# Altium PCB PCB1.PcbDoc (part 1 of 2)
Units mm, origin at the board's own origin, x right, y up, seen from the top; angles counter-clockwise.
Board outline 84 x 60 mm, 2 copper layers (Top Layer, Bottom Layer); 61 components, 46 nets, 218 pads, 307 vias.
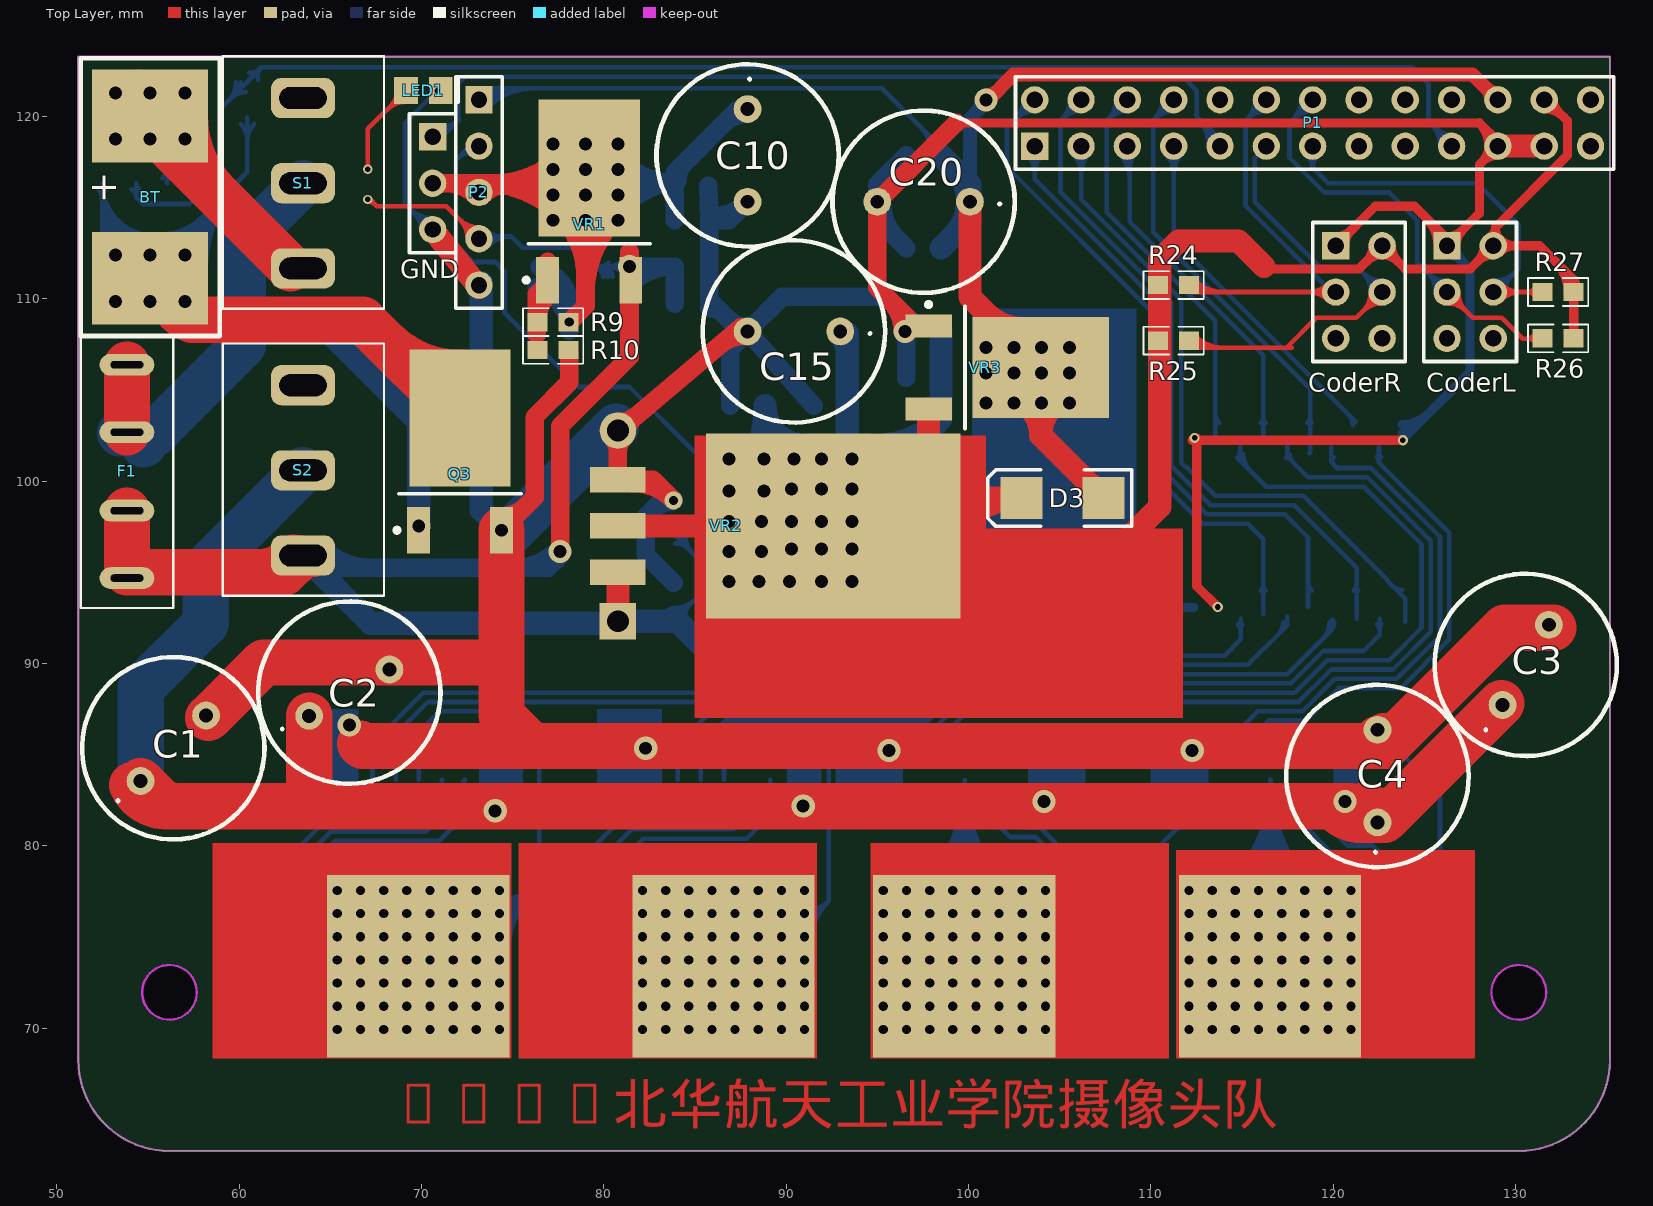
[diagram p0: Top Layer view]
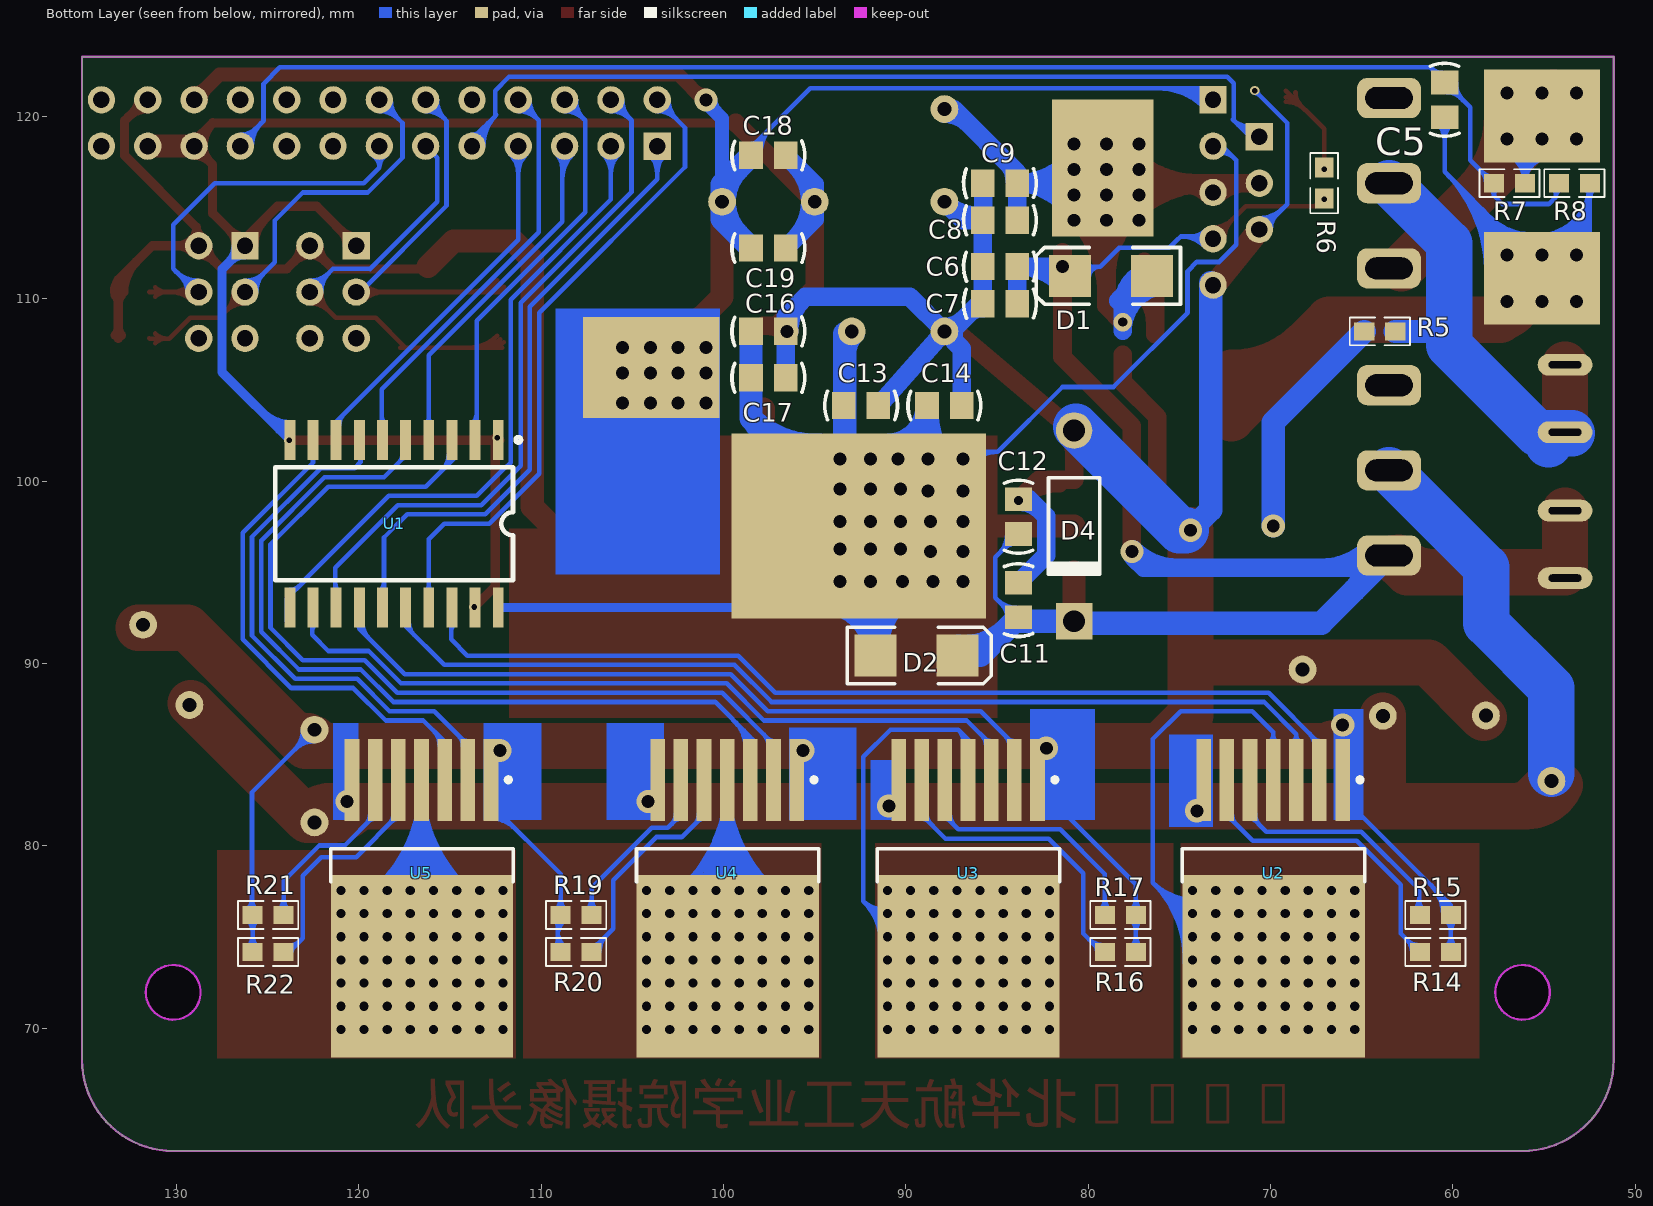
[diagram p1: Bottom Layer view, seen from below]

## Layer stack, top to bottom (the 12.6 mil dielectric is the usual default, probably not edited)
Top Layer: signal copper 0.0356
Dielectric: dielectric 0.32, FR-4, Dk 4.8
Bottom Layer: signal copper 0.0356

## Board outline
51.179,68.26 51.179,123.26 135.179,123.26 135.179,68.26 cw(c130.179,68.26) 130.179,63.26 56.179,63.26 cw(c56.179,68.26)
cut-out: 128.679,71.956 ccw(c130.179,71.956) 130.179,70.456 ccw(c130.179,71.956) 131.679,71.956 ccw(c130.179,71.956) 130.179,73.456 ccw(c130.179,71.956)
cut-out: 56.179,70.456 cw(c56.179,71.956) 54.679,71.956 cw(c56.179,71.956) 56.179,73.456 cw(c56.179,71.956) 57.679,71.956 cw(c56.179,71.956)

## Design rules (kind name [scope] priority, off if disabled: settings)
Clearance [All] p1: gap=0.254
ComponentClearance [All] p1 off: gap=0.254 collisioncheckmode=3 verticalgap=0.254 showdistances=FALSE
FabricationTestpoint [(IsPad And (OnTopLayer Or OnBottomLayer))] p1: side=3 testpointundercomponent=TRUE minsize=1.016 maxsize=2.54 preferedsize=1.524 minholesize=0 maxholesize=1.016 preferedholesize=0.813 testpointgrid=0.025 allowsidetop=TRUE allowsidebottom=TRUE usegrid=TRUE gridtolerance=0
HoleSize [All] p1: absolutevalues=TRUE maxlimit=5.08 minlimit=0.254 maxpercent=80.000 minpercent=20.000
PolygonConnect [All] p1: connectstyle=Relief reliefconductorwidth=0.254 reliefentries=4 polygonreliefangle="90 Angle"
RoutingVias [All] p1: holewidth=0.711 width=1.27 viastyle="Through Hole" minholewidth=0.305 minwidth=0.508 maxholewidth=0.711 maxwidth=1.27
SilkToSilkClearance [All] p1: silktosilkclearance=0
SilkscreenOverComponentPads [All] p1: minsilkscreentomaskgap=0
SolderMaskExpansion [All] p1: expansion=0.102
Width [All] p1: maxlimit=5.08 minlimit=0.254 preferedwidth=0.254
23 further rules are at their usual default settings.

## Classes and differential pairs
component class Driver: C1 C2 C3 C4 GND R14 R15 R16 R17 R19 R20 R21 R22 S2 U1 U2 U3 U4 U5
component class MCU: P1
component class Power: BT C5 C6 C7 C8 C9 C10 C11 C12 C13 C14 C15 C16 C17 C18 C19 C20 D1 D2 D3 D4 F1 LED1 P2 Q3 R5 R6 R7 R8 R9 R10 S1 VR1 VR2 VR3
component class Sensor: CoderL CoderR R24 R25 R26 R27

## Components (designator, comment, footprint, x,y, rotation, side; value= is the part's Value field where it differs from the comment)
BT "BAT" Header 55.118,115.57 r270 top
C1 "50V" C 56.388,85.344 r45 top locked
C2 "50V" C 66.04,88.392 r30 top locked
C3 "50V" C 130.556,89.916 r60 top locked
C4 "50V" C 122.428,83.82 r90 top locked
C5 "0805" C-RAD-0805 60.452,120.904 r270 bottom
C6 "Cap" C-RAD-0805 84.836,111.76 r180 bottom
C7 "Cap" C-RAD-0805 84.836,109.728 r180 bottom
C8 "Cap" C-RAD-0805 84.836,114.3 r180 bottom
C9 "Cap" C-RAD-0805 84.836,116.332 r180 bottom
C10 "16V" C 87.884,117.856 r270 top
C11 "Cap" C-RAD-0805 83.82,93.472 r270 bottom
C12 "Cap" C-RAD-0805 83.82,98.044 r270 bottom
C13 "Cap" C-RAD-0805 92.456,104.14 r0 bottom
C14 "Cap" C-RAD-0805 87.884,104.14 r0 bottom
C15 "16V" C 90.424,108.204 r180 top
C16 "Cap" C-RAD-0805 97.536,108.204 r0 bottom
C17 "Cap" C-RAD-0805 97.536,105.664 r0 bottom
C18 "Cap" C-RAD-0805 97.536,117.856 r0 bottom
C19 "Cap" C-RAD-0805 97.536,112.776 r0 bottom
C20 "16V" C 97.536,115.316 r180 top
CoderL "Header 3X2" HDR2X3 126.238,112.903 r270 top (schematic designator P6)
CoderR "Header 3X2" HDR2X3 120.142,112.903 r270 top (schematic designator P5)
D1 "Diode 1N5819" DIODE-SMB 78.74,111.252 r0 bottom
D2 "Diode 1N5819" DIODE-SMB 89.408,90.424 r180 bottom
D3 "Diode 1N5819" DIODE-SMB 105.156,99.06 r180 top
D4 "Diode 1N4007" DIO10.46-5.3x2.8 80.772,97.536 r270 bottom
F1 "10A" "保险丝  15A" 53.848,100.584 r270 top
GND "byBAT" HDR1X3 70.612,118.872 r270 top (schematic designator Servo1)
LED1 "GREEN" LED_0805 70.104,121.412 r0 top
P1 "toDriver" HDR2X13_CEN 103.632,118.364 r0 top
P2 "TEXT" HDR1X5 73.152,120.904 r270 top
Q3 "IR7843" IRLR7843 72.136,101.6 r90 top
R5 "Res1" 0603-1 64.008,108.204 r180 bottom
R6 "Res1" 0603-1 67.056,116.332 r270 bottom
R7 "Res1" 0603-1 56.896,116.332 r180 bottom
R8 "Res1" 0603-1 53.34,116.332 r0 bottom
R9 "Res1" 0603-1 77.216,108.712 r0 top
R10 "Res1" 0603-1 77.216,107.188 r180 top
R14 "Res1" 0603-1 60.96,74.168 r0 bottom locked
R15 "Res1" 0603-1 60.96,76.2 r0 bottom locked
R16 "Res1" 0603-1 78.232,74.168 r0 bottom locked
R17 "Res1" 0603-1 78.232,76.2 r0 bottom locked
R19 "Res1" 0603-1 108.077,76.2 r180 bottom locked
R20 "Res1" 0603-1 108.077,74.168 r180 bottom locked
R21 "Res1" 0603-1 124.968,76.2 r180 bottom locked
R22 "Res1" 0603-1 124.968,74.168 r180 bottom locked
R24 "Res1" 0603-1 111.252,110.744 r180 top
R25 "Res1" 0603-1 111.252,107.696 r180 top
R26 "Res1" 0603-1 132.334,107.823 r0 top
R27 "Res1" 0603-1 132.334,110.363 r0 top
S1 "ALL" BK1 63.5,116.332 r180 top
S2 "Motor" BK1 63.5,100.584 r180 top
U1 "74LS244" 74ALS244 111.252,102.108 r270 bottom
U2 "BTN_7971" BTN_7971B 65.564,81.28 r270 bottom locked
U3 "BTN_7971" BTN_7971B 82.296,81.28 r270 bottom locked
U4 "BTN_7971" BTN_7971B 95.504,81.28 r270 bottom locked
U5 "BTN_7971" BTN_7971B 112.268,81.28 r270 bottom locked
VR1 "AMS1085 adj" "AMS 1085CD" 79.248,115.316 r0 top
VR2 "AMS1085 5.0" TO-263-3L 81.788,97.536 r270 top
VR3 "AMS1085 3.3" "AMS 1085CD" 102.108,106.172 r270 top

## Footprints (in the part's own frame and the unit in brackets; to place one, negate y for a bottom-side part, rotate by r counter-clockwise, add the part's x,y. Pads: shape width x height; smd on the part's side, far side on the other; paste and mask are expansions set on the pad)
74ALS244 [mm]
  rect 2.2x0.6 smd: 1(-0.15,-1.1) 2(-0.15,-2.37) 3(-0.15,-3.64) 4(-0.15,-4.91) 5(-0.15,-6.18) 6(-0.15,-7.45) 7(-0.15,-8.72) 8(-0.15,-9.99) 9(-0.15,-11.26) 10(-0.15,-12.53) 11(9.05,-12.53) 12(9.05,-11.26) 13(9.05,-9.99) 14(9.05,-8.72) 15(9.05,-7.45) 16(9.05,-6.18) 17(9.05,-4.91) 18(9.05,-3.64) 19(9.05,-2.37) 20(9.05,-1.1)
  silkscreen extent -0.3,-13.34 7.55,0.15
0603-1 [mm] "贴片带丝印"
  rect 1.1x1 smd: 1(-0.85,0) 2(0.85,0)
  silkscreen extent -1.65,-0.76 1.65,0.76, body extent -1.14,-0.38 1.14,0.38, height 1
"AMS 1085CD" [mm]
  rect 1.25x2.55 smd: 1(-2.331,-4.3) 3(2.229,-4.3)
  rect 5.55x7.5 smd: 2(-0.051,1.85)
  rect 5.55x7.5 smd far side: 2(-0.051,1.854)
  silkscreen extent -3.63,-4.42 3.3,-2.3, body extent -3.43,-2.15 3.32,4.07, height 2.38
BK1 [mm]
  rrect50% 3.5x2.2 hole 1.2 slot 2.6 at 0 deg: 1(0,4.67) 2(0,0) 3(0,-4.67)
  silkscreen extent -4.45,-6.96 4.39,6.88
BTN_7971B [mm]
  rect 10x10 smd far side: 0(7.896,-4.267)
  rect 4.5x0.8 smd: 1(-2.334,-0.483) 2(-2.334,-1.753) 3(-2.334,-3.023) 4(-2.334,-4.293) 5(-2.334,-5.563) 6(-2.334,-6.833) 7(-2.334,-8.103)
  rect 10x10 smd: 8(7.896,-4.267)
  silkscreen extent -2.46,-9.27 3.25,0.73, body extent 1.45,-9.27 10.7,0.73, height 4.4
C [mil]
  round 60 hole 30: 1(-100,0) 2(100,0)
  silkscreen extent -197,-197 197,197
C-RAD-0805 [mm] "贴片电容"
  rect 1.3x1.5 smd: 1(-0.95,0) 2(0.95,0)
  silkscreen extent -2,-0.79 2,0.79, body extent -1.27,-0.64 1.27,0.64, height 0.9
DIO10.46-5.3x2.8 [mm] "Diode, Axial; Body 5.2 x 2.7 mm (LxDia. max), Lead Dia. 0.86 mm (max)"
  round 2 hole 1.2: 1(-5.23,0)
  rect 2x2 hole 1.2: 2(5.23,0)
  silkscreen extent -2.65,-1.4 2.75,1.4
DIODE-SMB [mm] "DO-214-AA/SMB; 2 C-Bend Leads; Body 5.3 x 3.6 mm, inc. leads (LxW)"
  rect 2.3x2.3 smd: 1(-2.25,0) 2(2.25,0)
  silkscreen extent -3.8,-1.55 4.1,1.55
HDR1X3 [mm] "Connector; Header; 3 Position"
  rect 1.5x1.5 hole 0.9: 1(0,0)
  round 1.5 hole 0.9: 2(2.54,0) 3(5.08,0)
  silkscreen extent -1.27,-1.27 6.35,1.27
HDR1X5 [mm] "Connector; Header; 5 Position"
  rect 1.5x1.5 hole 0.9: 1(0,0)
  round 1.5 hole 0.9: 2(2.54,0) 3(5.08,0) 4(7.62,0) 5(10.16,0)
  silkscreen extent -1.27,-1.27 11.43,1.27
HDR2X3 [mm] "Connector; Header; 3x2 Position"
  rect 1.5x1.5 hole 0.9: 1(0,0)
  round 1.5 hole 0.9: 2(0,2.54) 3(2.54,0) 4(2.54,2.54) 5(5.08,0) 6(5.08,2.54)
  silkscreen extent -1.27,-1.27 6.35,3.81
HDR2X13_CEN [mm] "Connector; Header; 13x2 Position"
  rect 1.5x1.5 hole 0.9: 1(0,0)
  round 1.5 hole 0.9: 2(2.54,0) 3(5.08,0) 4(7.62,0) 5(10.16,0) 6(12.7,0) 7(15.24,0) 8(17.78,0) 9(20.32,0) 10(22.86,0) 11(25.4,0) 12(27.94,0) 13(30.48,0) 14(0,2.54) 15(2.54,2.54) 16(5.08,2.54) 17(7.62,2.54) 18(10.16,2.54) 19(12.7,2.54) 20(15.24,2.54) 21(17.78,2.54) 22(20.32,2.54) 23(22.86,2.54) 24(25.4,2.54) 25(27.94,2.54) 26(30.48,2.54)
  silkscreen extent -1.06,-1.27 31.75,3.81
Header [mm]
  rect 5.08x6.35 smd: 1(-4.445,0) 2(4.445,0)
  rect 5.08x6.35 smd far side: 1(-4.445,0) 2(4.445,0)
  silkscreen extent -7.62,-3.81 7.62,3.81
IRLR7843 [mm]
  rect 2.55x1.25 smd: 1(-4.3,2.305) 3(-4.3,-2.255)
  rect 7.5x5.55 smd: 4(1.85,0.025)
  silkscreen extent -4.42,-3.32 -2.3,3.6, body extent -2.15,-3.35 4.07,3.4, height 2.38
LED_0805 [mm] "贴片二极管"
  rect 1.3x1.5 smd: 1(-0.95,0) 2(0.95,0)
  silkscreen extent 1.91,-0.64 1.91,0.64
TO-263-3L [mil]
  rect 55x120 smd: 1(-100,-40) 2(0,-40) 3(100,-40)
  rect 400x550 smd: 2(0,425)
  rect 400x550 smd far side: 2(0,425)
"保险丝  15A" [mm]
  oval 1.2x3 hole 0.4 slot 1.8 at 90 deg: 1(-5.79,0) 1(-2.09,0) 2(2.21,0) 2(5.91,0)
  silkscreen extent -7.44,-2.54 7.54,2.54

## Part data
BT: library part Header
C1 C2 C3 C4 C10 C15 C20: library part "Cap Pol1", "Polarized Capacitor (Radial)"
C5: library part "Cap Pol3", "Polarized Capacitor (Surface Mount)"
C6 C7 C8 C9 C11 C12 C13 C14 C16 C17 C18 C19: "无极性电容"
CoderL CoderR: "Header, 3-Pin, Dual row"
D1 D2 D3: library part "Diode 1N4007", "1 Amp General Purpose Rectifier"
D4: "1 Amp General Purpose Rectifier"
F1: library part "Fuse 1", "Fuse"
GND: library part "Header 3", "Header, 3-Pin"
LED1: library part LED2, "Typical RED, GREEN, YELLOW, AMBER GaAs LED"
P1: library part "Header 13X2A", "Header, 13-Pin, Dual row"
P2: library part "Header 5", "Header, 5-Pin"
Q3: library part MOSFET-N, "N-Channel MOSFET"
R5 R6 R7 R8 R9 R10 R14 R15 R16 R17 R19 R20 R21 R22 R24 R25 R26 R27: "贴片电阻"
S1 S2: library part SW-SPDT, "SPDT Subminiature Toggle Switch, Right Angle Mounting, Vertical Actuation"
VR1 VR2 VR3: library part AMS1085

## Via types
v1: diameter 0.762, hole 0.508, Top Layer to Bottom Layer, 224 vias
v2: diameter 1.27, hole 0.711, Top Layer to Bottom Layer, 75 vias
v3: diameter 0.559, hole 0.305, Top Layer to Bottom Layer, 3 vias
v4: diameter 0.508, hole 0.305, Top Layer to Bottom Layer, 3 vias
v5: diameter 1, hole 0.5, Top Layer to Bottom Layer, 2 vias

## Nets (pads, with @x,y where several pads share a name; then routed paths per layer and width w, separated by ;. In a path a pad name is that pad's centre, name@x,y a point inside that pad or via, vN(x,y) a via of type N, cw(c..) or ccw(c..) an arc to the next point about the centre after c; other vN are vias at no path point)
GND: C1.2 C2.2 C3.2 C4.2 C6.1 C7.1 C8.1 C9.1 C10.2 C11.1 C12.1 C13.1 C14.1 C15.2 C16.1 C17.1 C18.1 C19.1 C20.2 CoderL.1 CoderR.1 D4.1 GND.3 LED1.2 P1.11 P1.12 P2.5 Q3.3 R10.1 R14.1 R15.1 R16.1 R17.1 R19.1 R20.1 R21.1 R22.1 U1.1 U1.10 U1.19 U2.1 U3.1 U4.1 U5.1 VR2.1 VR3.1 | length 424.2
  Top Layer w0.508: 99.314,119.634 128.016,119.634 P1.11@129.032,118.618 ; v3@112.268,102.235 v3@112.522,102.235 ; v3@112.377,102.344 cw(c112.027,101.994) 112.522,101.994 ; v3@112.413,102.38 ccw(c112.763,102.73) 112.763,102.235 ; v3@112.522,102.362 v3@112.522,102.235 ; v3(113.665,93.091) 112.522,94.234 v3@112.522,102.235 ; CoderR.1@120.142,113.399 ccw(c120.142,114.596) 120.989,113.75 ccw(c121.835,112.903) CoderR.1@120.638,112.903 ; CoderR.1@120.269,113.03 122.301,115.062 124.46,115.062 126.238,113.284 CoderL.1@126.238,112.903 128.016,114.681 128.016,117.348 P1.11@129.032,118.364 ; v3(123.825,102.235) v3@112.522,102.235 ; 125.122,114.4 cw(c123.625,112.903) CoderL.1@125.742,112.903 ; CoderL.1@126.238,113.399 ccw(c126.238,114.596) 127.085,113.75 ccw(c127.931,112.903) CoderL.1@126.734,112.903 ; 128.006,119.644 cw(c126.725,118.364) 128.536,118.364 cw(c127.339,118.364) 128.185,117.517 cw(c129.032,116.671) P1.11@129.032,117.868 ; 128.619,119.031 ccw(c129.032,119.444) P1.11@129.032,118.86
  Top Layer w1.016: v2(74.391,97.3) 76.2,99.109 76.2,103.505 78.105,105.41 R10.1@78.105,106.934 ; Q3.3@74.391,98.067 ccw(c74.391,99.919) 75.7,98.609 ; D4.1@80.424,102.418 cw(c79.584,101.578) 80.772,101.578 cw(c81.96,101.578) D4.1@81.12,102.418 ; D4.1@80.772,102.766 D4.1@80.772,102.616 ; D4.1@80.813,103.256 ccw(c80.921,104.55) 81.76,103.559 ; D4.1@81.262,102.725 cw(c82.336,102.636) 81.64,103.458 ; VR2.1@81.597,99.885 cw(c81.597,96.819) v5@83.766,98.987 ; VR2.1@81.66,99.896 cw(c82.15,98.47) 83.217,99.536 ; v5@83.693,99.06 82.677,100.076 VR2.1@80.772,100.076 D4.1@80.772,102.616 ; 86.395,107.481 cw(c87.696,105.944) C15.2@87.863,107.951 ; C15.2@87.505,108.421 80.719,102.679 D4.1@80.772,102.616 ; 95.675,109.938 cw(c93.94,108.204) v2@96.393,108.204 ; VR3.1@96.61,108.114 cw(c97.548,107.176) VR3.1@97.548,108.503 ; VR3.1@97.808,108.503 97.11,108.503 94.996,110.617 C20.2@94.996,115.316 99.314,119.634
  Top Layer w1.27: GND.3@70.612,113.792 P2.5@73.152,110.617 ; P1.11@129.032,118.364 P1.12@131.572,118.364
  Top Layer w2.54: C1.2@58.311,87.013 61.341,90.043 74.041,90.043 ; 66.634,85.598 66.761,85.471 76.073,85.471 ; v2(74.391,97.3) 74.391,87.153 76.073,85.471 ; 121.508,85.471 ccw(c121.508,87.28) C4.2@122.787,86.001 ; C4.2@122.428,85.852 ccw(c122.428,87.964) 123.921,86.47 ; C3.2@132.08,91.948 129.399,91.948 122.922,85.471 76.073,85.471
  Bottom Layer w0.254: R14.1@59.846,74.432 ccw(c59.21,75.068) 60.11,75.068 ccw(c61.011,75.068) R14.1@60.374,74.432 ; R15.1@59.846,75.936 cw(c59.21,75.3) 60.11,75.3 cw(c61.011,75.3) R15.1@60.374,75.936 ; R15.1@60.025,76.2 cw(c61.14,76.2) 60.352,76.989 ; R15.1@60.071,76.2 60.11,76.161 R14.1@60.11,74.168 ; R15.1@60.11,76.2 60.11,76.747 65.786,82.423 U2.1@66.04,82.423 ; R15.1@60.279,76.2 cw(c62.008,76.2) 60.785,77.422 ; R15.1@60.533,76.2 cw(c62.875,76.2) 61.219,77.856 ; 69.332,114.945 ccw(c70.612,116.226) GND.3@70.612,114.415 ; 69.638,114.639 cw(c68.792,113.792) GND.3@69.989,113.792 ; 69.765,114.512 ccw(c70.612,115.358) GND.3@70.612,114.161 ; GND.3@70.612,113.792 70.485,113.792 69.088,115.189 69.088,119.634 v4@70.739,121.285 ; v4@70.739,121.412 cw(c70.432,121.412) 70.649,121.195 cw(c70.866,120.978) v4@70.866,121.285 ; R16.1@77.118,74.432 ccw(c76.482,75.068) 77.382,75.068 ccw(c78.283,75.068) R16.1@77.646,74.432 ; R17.1@77.118,75.936 cw(c76.482,75.3) 77.382,75.3 cw(c78.283,75.3) R17.1@77.646,75.936 ; R17.1@77.118,76.464 ccw(c76.482,77.1) 77.382,77.1 ccw(c78.283,77.1) R17.1@77.646,76.464 ; R16.1@77.382,74.168 77.382,75.985 R17.1@77.47,76.073 ; R17.1@77.382,76.2 77.382,77.89 82.042,82.55 U3.1@82.931,82.55 ; R19.1@108.663,76.464 ccw(c108.026,77.1) 108.927,77.1 ccw(c109.827,77.1) R19.1@109.191,76.464 ; R20.1@108.712,74.383 R20.1@108.927,74.168 109.093,74.334 R19.1@109.093,76.2 ; R20.1@108.713,74.432 ccw(c107.796,75.349) 109.093,75.349 ; R19.1@108.713,75.936 cw(c107.796,75.019) 109.093,75.019 ; R20.1@108.893,74.252 ccw(c108.41,74.735) 109.093,74.735 ; R19.1@108.893,76.116 cw(c108.41,75.633) 109.093,75.633 ; R20.1@108.927,73.953 R20.1@108.966,73.914 ; R19.1@108.927,76.2 108.927,78.447 U5.1@112.649,82.169 ; 109.093,74.788 ccw(c109.597,74.788) R20.1@109.241,74.432 ; 109.093,75.58 cw(c109.597,75.58) R19.1@109.241,75.936 ; 111.419,80.939 cw(c112.751,79.608) U5.1@112.751,81.491 ; 111.853,81.373 cw(c112.751,80.475) U5.1@112.751,81.745 ; 112.287,81.807 cw(c112.751,81.343) U5.1@112.751,81.999 ; U5.1@112.72,82.24 cw(c112.751,82.21) U5.1@112.751,82.253 ; C4.2@122.428,85.725 cw(c122.428,84.192) 123.512,85.276 cw(c124.596,86.36) C4.2@123.063,86.36 ; C4.2@122.428,85.979 cw(c122.428,85.059) 123.078,85.71 cw(c123.729,86.36) C4.2@122.809,86.36 ; C4.2@122.428,86.36 125.857,82.931 R21.1@125.857,76.239 ; R22.1@125.554,74.432 ccw(c124.917,75.068) 125.818,75.068 ccw(c126.718,75.068) R22.1@126.082,74.432 ; R21.1@125.554,75.936 cw(c124.917,75.3) 125.818,75.3 cw(c126.718,75.3) R21.1@126.082,75.936 ; R21.1@125.604,76.464 ccw(c124.994,77.074) 125.857,77.074 ; R21.1@125.818,76.2 125.818,74.207 R22.1@125.857,74.168 ; 125.857,77.127 ccw(c126.795,77.127) R21.1@126.132,76.464
  Bottom Layer w0.508: U1.10@123.782,102.258 127.496,105.972 127.496,111.621 126.492,112.625 CoderL.1@126.492,112.776 ; U1.10@123.782,102.596 ccw(c123.782,103.412) 124.359,102.835 ; U1.10@123.782,103.104 ccw(c123.782,105.146) 125.226,103.702 ; CoderL.1@126.238,112.407 cw(c126.238,111.267) 127.044,112.073 ; CoderL.1@126.734,112.903 ccw(c127.989,112.903) 127.102,112.015
  Bottom Layer w1.016: 82.662,98.414 cw(c83.72,97.356) C12.1@83.72,98.852 ; 82.743,98.495 cw(c83.82,97.419) C12.1@83.82,98.941 ; C11.1@83.82,94.422 82.308,95.934 82.308,98.06 83.242,98.994 C12.1@83.82,98.994 ; C9.1@85.725,116.205 C8.1@85.786,114.3 ; C7.1@85.786,109.486 cw(c85.786,108.436) 86.529,109.178 ; C8.1@85.797,114.542 ccw(c85.996,117.203) C10.2@87.884,115.316 86.868,114.3 C8.1@85.786,114.3 ; 86.8,108.907 ccw(c87.884,109.991) C15.2@87.884,108.458 ; C14.1@86.934,104.14 86.934,107.254 87.376,107.696 87.376,108.331 85.786,109.921 C6.1@85.786,111.76 C8.1@85.786,114.3 ; C13.1@91.506,104.14 C15.2@87.884,108.204 89.789,110.109 95.504,110.109 96.586,109.027 C17.1@96.586,105.664 ; 95.675,109.938 cw(c93.94,108.204) C16.1@96.393,108.204 ; 95.832,109.781 cw(c94.356,108.304) C16.1@96.444,108.304 ; C19.1@96.101,113.261 cw(c98.157,115.316) 95.25,115.316 cw(c98.157,115.316) C18.1@96.101,117.371 ; C19.1@96.586,112.776 94.996,114.366 C20.2@94.996,115.316 94.996,116.266 C18.1@96.586,117.856
  Bottom Layer w1.27: P2.5@73.279,110.871 73.279,98.412 v2(74.391,97.3)
  Bottom Layer w2.54: v2@74.641,97.3 74.995,97.3 D4.1@80.669,102.973
  other v2: 95.631,85.217 112.268,85.217 82.296,85.344 66.04,86.614 96.52,108.204
  other v3: 112.395,102.362
  other v4: 70.866,121.412
  other v5: 83.82,98.933
GND_BAT: BT.2 C5.2 Q3.4 R8.1 | length 137.6
  Top Layer w2.54: BT.2@54.483,112.395 ccw(c56.016,112.395) BT.2@54.932,111.311 ; BT.2@55.118,110.49 cw(c55.118,108.957) BT.2@56.202,110.041 ; BT.2@55.264,110.979 57.404,108.839 66.772,108.839 Q3.4@72.161,103.45 ; BT.2@56.574,109.406 ccw(c57.943,110.775) BT.2@57.943,108.839 ; 67.964,107.648 ccw(c72.111,111.795) Q3.4@72.111,105.93
  Bottom Layer w0.254: R8.1@52.226,116.068 cw(c51.59,115.432) 52.49,115.432 ; BT.2@52.451,113.157 52.49,113.196 R8.1@52.49,116.332 ccw(c55.357,116.332) BT.2@54.882,113.505 ; BT.2@52.49,113.33 ccw(c54.853,113.33) BT.2@54.462,111 ; BT.2@52.49,113.63 ccw(c54.903,113.63) BT.2@54.504,111.25 ; 52.49,113.931 ccw(c54.954,113.931) BT.2@54.546,111.501 ; 52.49,114.231 ccw(c55.004,114.231) BT.2@54.588,111.751 ; 52.49,114.531 ccw(c55.054,114.531) BT.2@54.63,112.002 ; 52.49,114.831 ccw(c55.105,114.831) BT.2@54.672,112.252 ; 52.49,115.131 ccw(c55.155,115.131) BT.2@54.714,112.503 ; 52.49,115.732 ccw(c55.256,115.732) BT.2@54.798,113.004 ; R8.1@52.49,116.032 ccw(c55.306,116.032) BT.2@54.84,113.254 ; R8.1@52.754,116.068 ccw(c53.391,115.432) 52.49,115.432 ; BT.2@54.756,112.753 cw(c55.206,115.431) 52.49,115.431 ; BT.2@55.118,111.125 BT.2@57.404,108.839 ; BT.2@55.436,110.807 ccw(c56.606,111.978) BT.2@56.925,110.353 ; BT.2@55.753,113.284 ccw(c55.753,115.737) 57.487,114.002 ; BT.2@55.753,113.538 ccw(c55.753,116.604) 57.921,114.436 ; BT.2@55.773,110.47 ccw(c56.717,111.415) BT.2@56.974,110.104 ; BT.2@56.11,110.133 ccw(c56.828,110.851) v2(57.023,109.855) ; BT.2@56.25,113.486 ccw(c56.481,114.588) 57.277,113.792 ; BT.2@56.388,111.144 cw(c60.336,111.265) 57.543,114.058 ; BT.2@56.642,111.152 cw(c61.142,111.289) 57.958,114.473 ; BT.2@56.748,112.822 ccw(c56.124,113.792) 57.277,113.792 ; BT.2@56.885,112.609 ccw(c56.423,113.326) BT.2@57.277,113.326 ; BT.2@56.895,111.16 cw(c61.949,111.314) 58.374,114.889 ; BT.2@57.149,111.168 cw(c62.755,111.339) 58.789,115.304 ; BT.2@57.277,113.008 ccw(c57.636,113.008) BT.2@57.382,112.754 ; BT.2@57.277,113.03 57.277,113.792 ; BT.2@57.277,113.271 ccw(c57.899,113.271) BT.2@57.459,112.831 ; BT.2@57.403,111.175 cw(c63.562,111.363) 59.205,115.72 ; BT.2@57.657,111.183 cw(c64.368,111.388) 59.621,116.136 ; BT.2@57.911,111.191 cw(c65.175,111.412) 60.036,116.551 ; BT.2@58.165,111.199 cw(c65.982,111.437) 60.452,116.967 ; C5.2@60.082,119.584 cw(c59.189,118.691) 60.452,118.691 cw(c61.715,118.691) C5.2@60.822,119.584 ; C5.2@60.452,119.954 60.452,116.967 ; 57.277,113.792 60.452,116.967
  other v2: 53.213,109.855 55.118,109.855 53.213,112.395 55.118,112.395 57.023,112.395
NetC5_1: C5.1 P1.10 R7.1 R8.2 | length 91.9
  Bottom Layer w0.254: R8.2@54.081,115.995 cw(c53.877,115.561) 54.356,115.561 ; 54.356,115.712 cw(c54.86,115.712) R8.2@54.504,116.068 ; R8.2@54.356,116.332 54.356,115.57 54.737,115.189 57.277,115.189 57.746,115.658 ; R7.1@57.548,116.016 cw(c57.324,115.658) 57.746,115.658 ; R7.1@57.746,116.332 57.746,115.658 ; R7.1@57.785,116.332 59.055,117.602 59.055,120.496 60.413,121.854 C5.1@60.452,121.854 ; R7.1@57.796,116.705 ccw(c57.796,117.579) 58.414,116.961 ; R7.1@57.944,116.016 ccw(c58.168,115.658) 57.746,115.658 ; R7.1@58.169,116.332 cw(c59.096,116.332) 58.441,116.988 ; 59.416,120.857 ccw(c58.419,121.854) C5.1@59.829,121.854 ; 59.564,121.004 cw(c60.352,120.216) C5.1@60.352,121.331 ; C5.1@59.85,121.29 ccw(c59.286,121.854) C5.1@60.083,121.854 ; C5.1@60.325,121.793 61.214,122.682 ; C5.1@60.552,122.377 ccw(c60.552,123.239) 61.161,122.629 ; C5.1@61.051,122.012 cw(c61.683,122.213) 61.214,122.682 ; 125.339,119.644 cw(c124.058,118.364) P1.10@125.869,118.364 ; 125.645,119.338 ccw(c126.492,120.184) P1.10@126.492,118.987 ; 125.772,119.211 cw(c124.926,118.364) P1.10@126.123,118.364 ; P1.10@126.492,118.364 126.492,118.491 125.222,119.761 125.222,121.793 124.333,122.682 61.214,122.682
NetF1_1: F1.1 R5.2 S1.2 | length 26.8
  Top Layer w0.254: F1.1@53.848,106.374 F1.1@54.154,106.68
  Top Layer w2.54: F1.1@53.848,102.674 F1.1@53.848,106.374
  Bottom Layer w0.254: F1.1@53.848,102.674 F1.1@54.668,102.674
  Bottom Layer w1.27: 60.322,108.204 R5.2@63.158,108.204
  Bottom Layer w2.54: F1.1@53.467,102.616 55.372,102.616 60.195,107.439 60.195,113.04 63.487,116.332 S1.2@63.5,116.332 ; 54.748,102.004 ccw(c54.748,102.034) 54.769,102.013
NetLED1_1: LED1.1 R6.1 | length 8.4
  Top Layer w0.254: v4@66.966,117.184 ccw(c66.749,117.401) 67.056,117.401 ccw(c67.363,117.401) v4@67.146,117.184 ; v4(67.056,117.094) 67.056,119.314 LED1.1@69.154,121.412 ; 68.09,120.348 cw(c69.154,119.285) LED1.1@69.154,120.789 ; 68.332,120.59 ccw(c67.61,121.312) LED1.1@68.631,121.312 ; LED1.1@68.524,120.782 cw(c69.154,120.152) LED1.1@69.154,121.043
NetP1_1: P1.1 U1.15 | length 38.3
  Bottom Layer w0.254: P1.1@103.191,117.923 cw(c102.128,116.86) 103.632,116.86 cw(c105.136,116.86) P1.1@104.073,117.923 ; P1.1@103.371,118.103 cw(c102.741,117.473) 103.632,117.473 cw(c104.523,117.473) P1.1@103.893,118.103 ; P1.1@103.632,118.364 103.632,116.542 110.617,109.557 110.617,100.617 113.063,98.171 117.348,98.171 118.618,96.901 U1.15@118.618,93.091 ; 118.618,94.478 ccw(c119.322,94.478) U1.15@118.824,93.98
NetP1_2: P1.2 U1.11 | length 40.9
  Bottom Layer w0.254: P1.2@105.731,117.923 cw(c104.668,116.86) 106.172,116.86 cw(c107.676,116.86) P1.2@106.613,117.923 ; P1.2@105.911,118.103 cw(c105.281,117.473) 106.172,117.473 cw(c107.063,117.473) P1.2@106.433,118.103 ; 106.172,115.57 106.172,115.824 ; P1.2@106.172,118.364 106.172,115.824 ; 123.263,94.246 ccw(c123.782,94.765) U1.11@123.782,94.031 ; U1.11@123.952,92.284 123.952,93.557 122.97,94.539 122.97,94.581 118.364,99.187 113.538,99.187 111.948,100.777 111.894,100.777 111.671,101 111.671,109.94 106.172,115.439 106.172,115.824
NetP1_3: P1.3 U1.4 | length 23.4
  Bottom Layer w0.254: P1.3@108.271,117.923 cw(c106.901,116.553) 108.839,116.553 ; P1.3@108.451,118.103 cw(c107.515,117.167) 108.839,117.167 cw(c109.909,117.167) P1.3@109.153,117.923 ; P1.3@108.712,118.364 108.839,118.237 108.839,114.209 116.162,106.886 U1.4@116.162,102.258 U1.4@116.162,102.065 ; U1.4@116.04,103.18 ccw(c115.744,103.476) 116.162,103.476 ccw(c116.58,103.476) U1.4@116.284,103.18
NetP1_4: P1.4 U1.8 | length 23.7
  Bottom Layer w0.254: P1.4@110.811,117.923 cw(c109.748,116.86) 111.252,116.86 cw(c112.756,116.86) P1.4@111.693,117.923 ; P1.4@110.991,118.103 cw(c110.361,117.473) 111.252,117.473 cw(c112.143,117.473) P1.4@111.513,118.103 ; P1.4@111.252,118.364 111.252,113.233 U1.8@121.242,103.243 ; 120.816,103.669 cw(c120.205,103.058) U1.8@121.069,103.058
NetP1_5: GND.1 P1.5 | length 56.5
  Bottom Layer w0.254: GND.1@70.612,118.872 71.12,118.872 72.072,119.825 cw(c71.118,120.779) GND.1@70.772,119.474 ; GND.1@70.641,118.983 ccw(c70.856,119.793) 71.448,119.2 ; GND.1@70.707,119.229 ccw(c70.987,120.286) 71.76,119.512 ; 72.021,119.761 72.021,121.812 72.383,122.174 111.76,122.174 112.522,121.412 112.522,120.015 113.665,118.872 P1.5@113.665,118.364 ; 112.459,120.078 cw(c110.745,118.364) P1.5@113.169,118.364 ; 112.893,119.644 cw(c111.612,118.364) P1.5@113.423,118.364 ; 113.326,119.211 cw(c112.48,118.364) P1.5@113.677,118.364 ; 113.379,119.158 ccw(c113.792,119.571) P1.5@113.792,118.987
NetP1_6: CoderR.4 P1.6 R25.1 | length 35.7
  Top Layer w0.254: R25.1@112.057,107.601 ccw(c112.746,108.29) 112.746,107.315 ; R25.1@112.141,107.315 117.729,107.315 ; R25.1@112.236,107.78 ccw(c113.359,108.903) 113.359,107.315 ; R25.1@112.416,107.96 ccw(c113.972,109.516) 113.972,107.315 ; 117.436,107.315 119.075,108.954 121.273,108.954 CoderR.4@122.682,110.363 ; CoderR.4@122.059,110.363 cw(c120.555,110.363) 121.618,109.299 cw(c122.682,108.236) CoderR.4@122.682,109.74 ; CoderR.4@122.313,110.363 cw(c121.422,110.363) 122.052,109.733 cw(c122.682,109.103) CoderR.4@122.682,109.994
  Bottom Layer w0.254: P1.6@116.332,118.364 115.697,117.729 115.697,115.309 119.377,111.63 ; 119.38,111.633 121.412,111.633 122.555,110.49 CoderR.4@122.682,110.49 ; CoderR.4@122.059,110.363 ccw(c120.555,110.363) 121.618,111.427 ccw(c122.682,112.49) CoderR.4@122.682,110.986 ; CoderR.4@122.313,110.363 ccw(c121.422,110.363) 122.052,110.993 ccw(c122.682,111.623) CoderR.4@122.682,110.732
NetP1_7: CoderL.4 P1.7 R27.1 | length 30.8
  Top Layer w0.254: CoderL.4@128.778,110.363 R27.1@131.484,110.363 ; CoderL.4@129.039,110.102 cw(c129.669,109.472) 129.669,110.363 cw(c129.669,111.254) CoderL.4@129.039,110.624 ; CoderL.4@129.219,109.922 cw(c130.282,108.859) 130.282,110.363 cw(c130.282,111.867) CoderL.4@129.219,110.804 ; R27.1@131.17,110.099 ccw(c130.534,109.463) 130.534,110.363 ccw(c130.534,111.263) R27.1@131.17,110.627
  Bottom Layer w0.254: P1.7@118.518,117.851 cw(c118.054,117.177) 118.872,117.177 ; P1.7@118.872,118.364 118.872,117.177 ; P1.7@119.226,117.851 ccw(c119.69,117.177) 118.872,117.177 ; CoderL.4@128.778,110.732 ccw(c128.778,111.929) 129.625,111.083 ; CoderL.4@128.778,110.986 ccw(c128.778,112.797) 130.058,111.516 ; CoderL.4@128.905,110.363 130.175,111.633 130.175,114.046 127.889,116.332 119.717,116.332 118.872,117.177 ; CoderL.4@129.401,110.363 cw(c130.598,110.363) 129.752,111.21
NetP1_14: P1.14 U1.17 | length 40.5
  Bottom Layer w0.254: P1.14@103.009,120.904 cw(c101.505,120.904) 102.568,119.84 cw(c103.632,118.777) P1.14@103.632,120.281 ; P1.14@103.263,120.904 cw(c102.372,120.904) 103.002,120.274 cw(c103.632,119.644) P1.14@103.632,120.535 ; P1.14@103.632,120.904 102.108,119.38 102.108,117.221 110.109,109.22 110.109,100.407 112.853,97.663 115.316,97.663 116.162,96.817 U1.17@116.162,92.71 ; U1.17@116.04,93.98 ccw(c115.744,94.276) 116.162,94.276 ccw(c116.58,94.276) U1.17@116.284,93.98
NetP1_15: P1.15 U1.13 | length 42.8
  Bottom Layer w0.254: P1.15@105.549,120.904 cw(c104.045,120.904) 105.108,119.84 cw(c106.172,118.777) P1.15@106.172,120.281 ; P1.15@105.803,120.904 cw(c104.912,120.904) 105.542,120.274 cw(c106.172,119.644) P1.15@106.172,120.535 ; P1.15@106.172,120.904 105.041,119.773 105.041,115.852 111.125,109.768 111.125,100.828 113.274,98.679 117.856,98.679 121.285,95.25 U1.13@121.285,92.453 ; U1.13@121.12,93.98 ccw(c120.721,94.379) 121.285,94.379 ; 121.285,94.172 ccw(c121.556,94.172) U1.13@121.364,93.98
NetP1_16: P1.16 U1.2 | length 25.9
  Bottom Layer w0.254: P1.16@108.089,120.904 cw(c106.585,120.904) 107.648,119.84 cw(c108.712,118.777) P1.16@108.712,120.281 ; P1.16@108.343,120.904 cw(c107.452,120.904) 108.082,120.274 cw(c108.712,119.644) P1.16@108.712,120.535 ; P1.16@108.712,120.904 107.581,119.773 107.581,114.749 113.538,108.792 U1.2@113.538,102.235 ; 113.538,103.678 ccw(c114.242,103.678) U1.2@113.744,103.18
NetP1_17: P1.17 U1.6 | length 27.9
  Bottom Layer w0.254: P1.17@110.629,120.904 cw(c109.125,120.904) 110.188,119.84 cw(c111.252,118.777) P1.17@111.252,120.281 ; P1.17@110.883,120.904 cw(c109.992,120.904) 110.622,120.274 cw(c111.252,119.644) P1.17@111.252,120.535 ; P1.17@111.252,120.904 110.121,119.773 110.121,113.646 118.745,105.022 118.745,101.559 U1.6@118.702,101.516 ; U1.6@118.58,103.18 ccw(c118.181,103.579) 118.745,103.579 ; 118.745,103.372 ccw(c119.016,103.372) U1.6@118.824,103.18
NetP1_19: CoderR.3 P1.19 R24.1 | length 32.9
  Top Layer w0.254: R24.1@112.014,110.617 112.268,110.363 CoderR.3@120.142,110.363 ; R24.1@112.057,110.649 ccw(c112.746,111.338) 112.746,110.363 ; R24.1@112.236,110.828 ccw(c113.359,111.951) 113.359,110.363 ; R24.1@112.416,111.008 ccw(c113.972,112.564) 113.972,110.363 ; CoderR.3@119.701,109.922 ccw(c118.638,108.859) 118.638,110.363 ccw(c118.638,111.867) CoderR.3@119.701,110.804 ; CoderR.3@119.881,110.102 ccw(c119.251,109.472) 119.251,110.363 ccw(c119.251,111.254) CoderR.3@119.881,110.624
  Bottom Layer w0.254: P1.19@115.709,120.904 cw(c114.205,120.904) 115.268,119.84 cw(c116.332,118.777) P1.19@116.332,120.281 ; P1.19@115.963,120.904 cw(c115.072,120.904) 115.702,120.274 cw(c116.332,119.644) P1.19@116.332,120.535 ; P1.19@116.459,121.031 P1.19@116.332,120.904 115.189,119.761 115.189,115.099 119.925,110.363 CoderR.3@120.142,110.363
NetP1_20: CoderL.3 P1.20 R26.1 | length 35.9
  Top Layer w0.254: CoderL.3@126.238,109.74 cw(c126.238,108.236) 127.302,109.299 cw(c128.365,110.363) CoderL.3@126.861,110.363 ; CoderL.3@126.238,109.994 cw(c126.238,109.103) 126.868,109.733 cw(c127.498,110.363) CoderL.3@126.607,110.363 ; CoderL.3@126.238,110.363 127.647,108.954 129.246,108.954 130.389,107.811 131.472,107.811 R26.1@131.484,107.823 ; 130.505,107.811 ccw(c130.505,108.752) R26.1@131.17,108.087 ; 130.562,107.811 cw(c130.562,106.951) R26.1@131.17,107.559
  Bottom Layer w0.254: P1.20@118.249,120.904 cw(c116.745,120.904) 117.808,119.84 cw(c118.872,118.777) P1.20@118.872,120.281 ; P1.20@118.503,120.904 cw(c117.612,120.904) 118.242,120.274 cw(c118.872,119.644) P1.20@118.872,120.535 ; P1.20@118.872,120.904 117.602,119.634 117.602,117.729 119.507,115.824 123.063,115.824 124.599,114.288 124.599,112.002 CoderL.3@126.238,110.363 CoderL.3@126.365,110.236 ; CoderL.3@125.615,110.363 ccw(c124.111,110.363) 125.174,111.427 ccw(c126.238,112.49) CoderL.3@126.238,110.986 ; CoderL.3@125.869,110.363 ccw(c124.978,110.363) 125.608,110.993 ccw(c126.238,111.623) CoderL.3@126.238,110.732
NetQ3_1: Q3.1 R5.1 | length 12.7
  Bottom Layer w1.27: R5.1@64.858,108.204 69.85,103.212 v2(69.85,97.536)
NetR9_1: R9.1 R10.2 VR1.1 | length 6
  Top Layer w1.016: 76.322,108.061 76.322,110.231 76.917,110.826 VR1.1@76.917,112.014 ; R9.1@76.322,108.645 cw(c78.638,108.645) VR1.1@77,110.283
NetR14_2: R14.2 U2.6 | length 19.4
  Bottom Layer w0.254: R14.2@61.86,74.541 ccw(c61.86,75.415) 62.478,74.797 ; R14.2@61.976,74.295 62.865,75.184 62.865,77.851 65.278,80.264 70.966,80.264 72.263,81.561 72.263,83.48 U2.6@72.397,83.614 ; R14.2@62.233,74.168 cw(c63.16,74.168) 62.505,74.824 ; 71.882,81.18 ccw(c71.298,81.764) U2.6@72.124,81.764 ; 72.048,81.346 cw(c72.397,80.998) U2.6@72.397,81.491
NetR15_2: R15.2 U2.5 | length 16.8
  Bottom Layer w0.254: R15.2@61.596,76.464 ccw(c60.986,77.074) 61.849,77.074 ; R15.2@61.849,76.2 61.849,77.597 65.024,80.772 70.231,80.772 71.127,81.668 U2.5@71.127,83.614 ; 61.849,77.127 ccw(c62.787,77.127) R15.2@62.124,76.464 ; 70.593,81.134 ccw(c69.962,81.764) U2.5@70.854,81.764 ; U2.5@70.825,81.366 cw(c71.127,81.064) U2.5@71.127,81.491
NetR16_2: R16.2 U3.6 | length 19.3
  Bottom Layer w0.254: R16.2@79.132,74.541 ccw(c79.132,75.722) 79.967,74.887 ; R16.2@79.248,74.168 80.264,75.184 80.264,78.486 82.169,80.391 87.825,80.391 89.129,81.695 U3.6@89.129,83.614 ; R16.2@79.505,74.168 cw(c80.125,74.168) 79.687,74.607 ; 88.614,81.18 ccw(c88.03,81.764) U3.6@88.856,81.764 ; 88.78,81.346 cw(c89.129,80.998) U3.6@89.129,81.491
NetR17_2: R17.2 U3.5 | length 14.8
  Bottom Layer w0.254: R17.2@78.818,76.464 ccw(c78.182,77.1) 79.082,77.1 ccw(c79.982,77.1) R17.2@79.346,76.464 ; R17.2@79.082,76.2 79.082,78.447 81.534,80.899 87.122,80.899 U3.5@87.884,81.661 ; 87.302,81.079 ccw(c86.617,81.764) U3.5@87.586,81.764 ; U3.5@87.611,81.388 cw(c87.859,81.141) U3.5@87.859,81.491
NetR19_2: R19.2 U4.6 | length 10.6
  Bottom Layer w0.254: U4.6@102.337,81.491 cw(c102.337,80.998) 102.685,81.346 ; U4.6@102.362,81.661 102.371,81.661 103.049,80.983 103.929,80.983 107.227,77.685 R19.2@107.227,76.073 ; U4.6@102.61,81.764 ccw(c103.435,81.764) 102.851,81.18 ; R19.2@106.963,76.464 ccw(c106.327,77.1) 107.227,77.1 ccw(c108.127,77.1) R19.2@107.491,76.464
NetR20_2: R20.2 U4.5 | length 13.9
  Bottom Layer w0.254: U4.5@101.067,81.491 cw(c101.067,81.019) 101.401,81.352 ; U4.5@101.092,81.661 102.278,80.475 103.675,80.475 106.045,78.105 106.045,75.438 107.227,74.256 R20.2@107.227,74.041 ; U4.5@101.34,81.764 ccw(c102.186,81.764) 101.587,81.166 ; 106.443,75.04 cw(c105.57,74.168) R20.2@106.804,74.168 ; 106.776,74.707 ccw(c107.177,75.108) R20.2@107.177,74.541 ; R20.2@106.876,74.607 cw(c106.438,74.168) R20.2@107.058,74.168
NetR21_2: R21.2 U5.6 | length 10.8
  Bottom Layer w0.254: U5.6@119.101,81.491 cw(c119.101,81.019) 119.435,81.352 ; U5.6@119.126,81.661 120.777,80.01 122.174,80.01 124.118,78.066 R21.2@124.118,76.2 ; U5.6@119.374,81.764 ccw(c120.22,81.764) 119.621,81.166 ; R21.2@123.854,76.464 ccw(c123.218,77.1) 124.118,77.1 ccw(c125.018,77.1) R21.2@124.382,76.464
NetR22_2: R22.2 U5.5 | length 14.2
  Bottom Layer w0.254: U5.5@117.729,81.661 117.856,81.661 120.142,79.375 122.047,79.375 123.063,78.359 123.063,74.93 123.825,74.168 R22.2@124.118,74.168 ; U5.5@117.831,81.491 cw(c117.831,81.019) 118.165,81.352 ; U5.5@118.104,81.764 ccw(c118.95,81.764) 118.351,81.166 ; 123.185,74.808 ccw(c123.867,75.491) R22.2@124.012,74.537 ; 123.54,74.453 ccw(c123.961,74.874) R22.2@124.05,74.286 ; R22.2@123.603,74.39 cw(c123.381,74.168) R22.2@123.695,74.168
